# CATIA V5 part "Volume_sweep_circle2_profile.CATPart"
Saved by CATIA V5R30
Part number: Part1
Bounding box of the stored display mesh (mm): x -183.601 to 0, y -55 to 90.724, z -55 to 54.977
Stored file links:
  D:\PROJECTS\CATIA V56R 2020\Resources\Parts File\c17_catia_v6_6r2020_prt\Volume_sweep_circle2_profile.CATPart
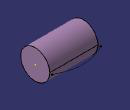
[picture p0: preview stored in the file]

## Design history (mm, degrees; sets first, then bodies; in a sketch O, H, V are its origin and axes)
Set1
  Sketch1 on xy-plane, origin (0, 0, 0), H (1, 0, 0), V (0, 1, 0)
    line L1 (0, 0) -> (-183.1008, 0)
    horizontal: L1 H
  Sketch2 on xy-plane, origin (0, 0, 0), H (1, 0, 0), V (0, 1, 0)
    spline S1 through (0, 65.5148) (-89.6654, 90.7245) (-183.6013, 65.5148)
    point P1 (0, 65.5148)
    coincidence: P1 V
  Sweep1: type Circle, Guide Sketch1, Reference Sketch2, Radius 55
Body1 (main body)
